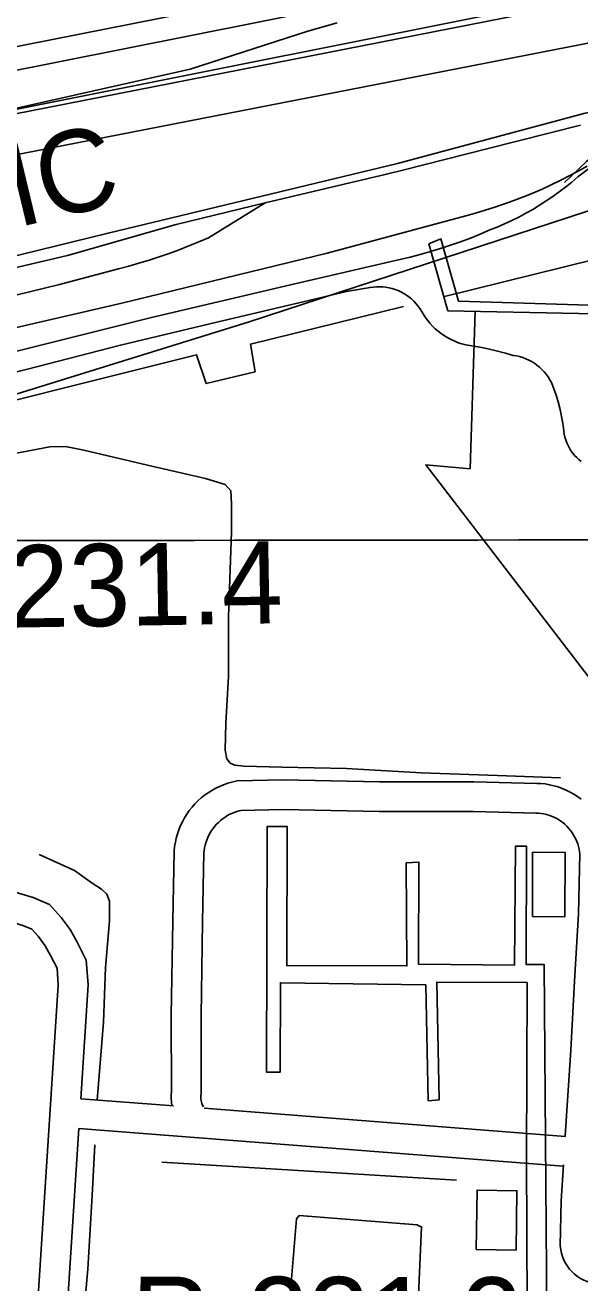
# Model space of a CAD drawing. Extents: x 3313447 to 3351316, y 703786 to 729172.
# Drawn here: x 3320817 to 3321377, y 720543 to 721813 of the extents above; entities that cross this region are included whole.
import ezdxf

# ---------------------------------------------------------------- set-up
doc = ezdxf.new("R2010")
doc.units = 0
for name, color, linetype in [('V-BLDG-OTLN', 7, 'Continuous'), ('V-DTCH-CNTR', 7, 'Continuous'), ('V-GRID-MAJR', 7, 'Continuous'), ('V-RAIL-IDEN', 7, 'Continuous'), ('V-RAIL-TRAK', 7, 'Continuous'), ('V-RIVR-RANG-IDEN', 7, 'Continuous'), ('V-ROAD-CNTR', 7, 'Continuous'), ('V-SITE-OTLN', 7, 'Continuous'), ('V-SITE-VEGE', 7, 'Continuous'), ('V-TOPO-SHOR', 7, 'Continuous'), ('V-UTIL-LINE', 7, 'Continuous')]:
    doc.layers.add(name, color=color, linetype=linetype)

msp = doc.modelspace()

# ---------------------------------------------------------------- linework, layer by layer
at = {"layer": 'V-BLDG-OTLN'}
for points in [[(3321329.251, 720912.969), (3321329.421, 720977.929), (3321362.312, 720977.843), (3321362.146, 720912.883)], [(3321272.464, 720576.802), (3321273.441, 720636.827), (3321313.668, 720636.171), (3321312.691, 720576.147)]]:
    msp.add_lwpolyline(points, close=True, dxfattribs=at)
at = {"layer": 'V-DTCH-CNTR'}
for points in [[(3320715.056, 721440.591), (3320817.772, 721465.376), (3320913.178, 721490.181), (3321010.318, 721513.2440000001), (3321104.676, 721535.6140000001), (3321141.233, 721544.22), (3321165.254, 721548.332), (3321168.418, 721548.775), (3321171.605, 721549.0160000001), (3321174.799, 721549.057), (3321177.992, 721548.897), (3321181.167, 721548.535), (3321184.312, 721547.974), (3321187.417, 721547.214), (3321190.467, 721546.26), (3321193.451, 721545.115), (3321196.357, 721543.786), (3321199.171, 721542.274), (3321201.886, 721540.589), (3321204.489, 721538.733), (3321206.969, 721536.718), (3321209.318, 721534.551), (3321211.524, 721532.2390000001), (3321213.58, 721529.794), (3321215.481, 721527.223), (3321217.211, 721524.539), (3321218.77, 721521.747), (3321220.892, 721518.464), (3321223.194, 721515.304), (3321225.67, 721512.281), (3321228.312, 721509.402), (3321231.113, 721506.676), (3321234.0640000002, 721504.1140000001), (3321237.1550000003, 721501.7220000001), (3321240.376, 721499.508), (3321243.717, 721497.478), (3321247.168, 721495.6410000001), (3321250.715, 721494.003), (3321254.352, 721492.5650000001), (3321258.063, 721491.336), (3321261.835, 721490.321), (3321269.9390000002, 721489.071), (3321278.0100000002, 721487.617), (3321286.043, 721485.956), (3321294.028, 721484.093), (3321301.96, 721482.024), (3321309.828, 721479.757), (3321313.076, 721479.237), (3321316.281, 721478.504), (3321319.433, 721477.561), (3321322.518, 721476.417), (3321325.52, 721475.071), (3321328.426, 721473.531), (3321331.2260000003, 721471.807), (3321333.907, 721469.9), (3321336.4560000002, 721467.821), (3321338.865, 721465.581), (3321341.122, 721463.187), (3321343.215, 721460.649), (3321345.1380000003, 721457.983), (3321346.883, 721455.193), (3321348.4390000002, 721452.295), (3321350.938, 721445.93), (3321353.1950000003, 721439.479), (3321355.208, 721432.946), (3321356.977, 721426.341)], [(3321356.977, 721426.341), (3321358.4990000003, 721419.679), (3321359.769, 721412.961), (3321360.787, 721406.203), (3321361.0300000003, 721403.1900000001), (3321361.4790000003, 721400.2000000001), (3321362.13, 721397.2490000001), (3321362.978, 721394.3470000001), (3321364.02, 721391.511), (3321365.253, 721388.75), (3321366.6720000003, 721386.079), (3321368.268, 721383.511), (3321370.0330000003, 721381.058), (3321371.9620000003, 721378.7270000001), (3321374.043, 721376.536), (3321376.269, 721374.49), (3321378.631, 721372.5970000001)]]:
    msp.add_lwpolyline(points, dxfattribs=at)
at = {"layer": 'V-GRID-MAJR'}
msp.add_spline([(3317583.083, 721289.311), (3322833.044, 721295.0380000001), (3328083.005, 721301.528), (3333332.965, 721308.783), (3338582.924, 721316.8), (3343832.882, 721325.582), (3349082.838, 721335.127), (3349082.839, 721335.127)], degree=3, dxfattribs=at)
at = {"layer": 'V-RAIL-TRAK'}
for points in [[(3321377.887, 721712.283), (3321283.29, 721688.235), (3321199.705, 721667.135), (3321181.822, 721662.621), (3321059.225, 721633.8910000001), (3320969.3850000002, 721611.9450000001), (3320859.455, 721580.5430000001), (3320596.289, 721518.909)], [(3321419.0300000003, 721692.636), (3321375.11, 721660.006), (3321369.007, 721654.791), (3321362.765, 721649.747), (3321356.387, 721644.875), (3321349.879, 721640.179), (3321343.2430000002, 721635.661), (3321336.487, 721631.327), (3321329.616, 721627.1780000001), (3321322.634, 721623.221), (3321315.546, 721619.455), (3321308.358, 721615.883), (3321301.075, 721612.512), (3321293.702, 721609.338), (3321286.245, 721606.368), (3321276.452, 721602.184), (3321266.5700000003, 721598.213), (3321256.607, 721594.455), (3321246.563, 721590.914), (3321236.446, 721587.59), (3321226.2600000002, 721584.488), (3321216.007, 721581.604), (3321205.696, 721578.942), (3321195.3310000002, 721576.502), (3321084.886, 721550.911), (3320944.3200000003, 721518.003), (3320804.275, 721482.985)], [(3321384.47, 721670.88), (3321375.563, 721665.887), (3321366.556, 721661.077), (3321357.452, 721656.448), (3321348.259, 721652.008), (3321338.973, 721647.754), (3321329.606, 721643.691), (3321320.156, 721639.818), (3321310.631, 721636.14), (3321301.032, 721632.657), (3321291.365, 721629.367), (3321281.631, 721626.277), (3321271.84, 721623.383), (3321261.989, 721620.6900000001), (3321121.9390000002, 721583.029), (3320914.253, 721532.341), (3320784.256, 721502.576)], [(3320764.0300000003, 721530.027), (3320851.2260000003, 721551.453), (3320910.9450000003, 721567.143), (3320921.306, 721569.828), (3320931.612, 721572.72), (3320941.858, 721575.814), (3320952.041, 721579.1140000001), (3320962.156, 721582.612), (3320972.199, 721586.31), (3320982.169, 721590.21), (3320992.058, 721594.304), (3321001.864, 721598.594), (3321059.225, 721633.8910000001)]]:
    msp.add_lwpolyline(points, dxfattribs=at)
at = {"layer": 'V-ROAD-CNTR'}
for points in [[(3321599.017764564, 721774.9144231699), (3321486.4609896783, 721744.793483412), (3321382.659197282, 721724.407524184), (3321193.099576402, 721673.40962618), (3320900.4761616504, 721603.2987664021), (3320354.97225266, 721469.442034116), (3319853.704255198, 721345.2962824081), (3319482.2569980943, 721260.223452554), (3319347.642267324, 721225.1355227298), (3319071.498819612, 721155.4696620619), (3318801.6813592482, 721085.8358013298), (3318597.173768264, 721038.4098961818), (3318497.648967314, 721012.8879472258), (3318053.893854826, 720830.5203119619), (3317615.848730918, 720718.779535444), (3317581.334799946, 720710.5405519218)], [(3321378.57428082, 721031.4875044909), (3321375.0071688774, 721034.1262927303), (3321371.28895144, 721036.548881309), (3321367.4405012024, 721038.7463913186), (3321363.4667680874, 721040.7157744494), (3321359.3808405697, 721042.4483276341), (3321355.1983168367, 721043.9378909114), (3321350.941316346, 721045.1750426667), (3321346.6156204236, 721046.1630950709), (3321342.2369128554, 721046.8916300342), (3321337.828875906, 721047.3622700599), (3321333.666936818, 721047.5592849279), (3321269.9803972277, 721049.1241932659), (3321174.6075424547, 721049.0241609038), (3321077.0315982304, 721051.0202282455), (3321031.016589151, 721050.0519076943), (3321025.655509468, 721048.8433852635), (3321021.415429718, 721047.6289212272), (3321017.2572432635, 721046.1780743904), (3321013.188651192, 721044.497165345), (3321009.21795251, 721042.5867699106), (3321005.3637048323, 721040.455845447), (3321001.6323991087, 721038.1079740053), (3320998.0485367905, 721035.5567290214), (3320994.607112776, 721032.8085414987), (3320991.322880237, 721029.8606759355), (3320988.220311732, 721026.7407884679), (3320985.2970420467, 721023.453964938), (3320982.5587376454, 721020.0007276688), (3320980.020551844, 721016.3967021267), (3320977.69109692, 721012.6559444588), (3320975.5778403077, 721008.7898988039), (3320973.6876975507, 721004.8140385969), (3320972.0244740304, 721000.7388934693), (3320970.591017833, 720996.5698527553), (3320969.3976520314, 720992.3267743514), (3320968.4466708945, 720988.0287853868), (3320967.7399331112, 720983.6843902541), (3320967.253750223, 720979.0741251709), (3320966.0162567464, 720908.1271908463), (3320964.374753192, 720812.9940977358), (3320964.5216596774, 720735.9704318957), (3320964.2795957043, 720733.3925458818), (3320964.220828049, 720729.4966803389), (3320964.4664734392, 720725.6249091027), (3320964.9928644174, 720721.8873942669)], [(3321362.4572764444, 720690.905246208), (3321362.504857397, 720691.683104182), (3321367.9460574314, 720777.9365712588), (3321371.9541898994, 720847.8330040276), (3321375.941550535, 720915.7396278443), (3321377.1211383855, 720976.417861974), (3321376.8887279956, 720978.5487935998), (3321376.4426553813, 720981.1786695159), (3321375.8444354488, 720983.7739544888), (3321375.0904538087, 720986.3325356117), (3321374.187089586, 720988.8506633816), (3321373.140025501, 720991.3020693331), (3321371.949876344, 720993.6891255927), (3321370.620806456, 720996.001662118), (3321369.157127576, 720998.2347491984), (3321367.566509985, 721000.373829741), (3321365.8534179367, 721002.4140826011), (3321364.0187064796, 721004.3540212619), (3321362.0751408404, 721006.1818895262), (3321360.0257191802, 721007.8924955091), (3321357.8828311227, 721009.4777072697), (3321355.6490485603, 721010.933118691), (3321353.329498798, 721012.2576086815), (3321350.9392319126, 721013.4422255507), (3321348.483159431, 721014.4836723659), (3321345.971683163, 721015.3781090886), (3321343.408683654, 721016.1229573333), (3321340.8083795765, 721016.7169049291), (3321338.179087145, 721017.1543699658), (3321335.525124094, 721017.4377299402), (3321332.589063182, 721017.5767150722), (3321269.6276027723, 721019.1238067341), (3321174.3164575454, 721019.0238390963), (3321077.04040177, 721021.0137717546), (3321034.6674108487, 721020.1220923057), (3321033.090490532, 721019.7666147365), (3321030.494570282, 721019.0230787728), (3321027.9347567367, 721018.1299256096), (3321025.4293488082, 721017.094834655), (3321022.99004749, 721015.9212300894), (3321020.6222951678, 721014.612154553), (3321018.3336008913, 721013.1720259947), (3321016.12146321, 721011.5972709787), (3321014.0028872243, 721009.9054585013), (3321011.9951197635, 721008.1033240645), (3321010.081688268, 721006.1792115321), (3321008.2769579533, 721004.1500350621), (3321006.5952623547, 721002.0292723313), (3321005.037448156, 720999.8172978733), (3321003.60690308, 720997.5200555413), (3321002.308159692, 720995.1441011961), (3321001.144302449, 720992.6959614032), (3321000.1195259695, 720990.1851065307), (3320999.238982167, 720987.6241472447), (3320998.5063479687, 720985.0192256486), (3320997.9213291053, 720982.3752146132), (3320997.486066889, 720979.699609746), (3320997.226249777, 720977.2358748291), (3320996.0117432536, 720907.6068091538), (3320994.375246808, 720812.7639022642), (3320994.5243403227, 720734.5935681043), (3320994.258404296, 720731.7614541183), (3320994.2351719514, 720730.2213196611), (3320994.333526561, 720728.6710908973), (3320994.5502048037, 720727.1326182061), (3320994.883807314, 720725.6299909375), (3320995.3372757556, 720724.1480902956), (3320995.9035223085, 720722.705387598), (3320996.8335828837, 720720.792813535)], [(3320872.810216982, 720729.049514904), (3320880.2292021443, 720843.963285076), (3320878.395205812, 720869.115234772), (3320868.79622501, 720887.7441975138), (3320862.117238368, 720899.8461733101), (3320853.0932564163, 720912.07614885), (3320841.425279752, 720925.084122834), (3320824.705313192, 720932.3221083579), (3320800.7973610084, 720939.4320941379), (3320695.338571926, 720945.7020815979), (3320337.6882872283, 720967.9610370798), (3319663.292636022, 721016.2849404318), (3319634.021694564, 721018.9899350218), (3319621.0377205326, 721011.3589502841), (3319607.3897478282, 721001.008970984), (3319598.1027664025, 720988.234996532), (3319586.190790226, 720969.4510340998), (3319577.4098077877, 720951.9500691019), (3319567.714827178, 720725.8495213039), (3319552.01885857, 720445.6400817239), (3319549.110864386, 720392.5861878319)], [(3320796.6763692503, 720012.983947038), (3320811.634339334, 720247.1364787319), (3320850.159262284, 720843.8392853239), (3320848.92126476, 720860.82125136), (3320842.324277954, 720873.6222257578), (3320836.805288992, 720883.6222057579), (3320829.8033029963, 720893.1121867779), (3320823.479315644, 720900.162172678), (3320814.4333337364, 720904.0781648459), (3320795.5633714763, 720909.690153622), (3320693.51657557, 720915.758141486), (3320335.684291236, 720938.0270969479), (3319660.8406409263, 720986.383000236), (3319640.887680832, 720988.2279965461), (3319637.759687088, 720986.3890002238), (3319629.0477045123, 720979.7830134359), (3319622.926716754, 720971.365030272), (3319612.330737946, 720954.6550636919), (3319607.107748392, 720944.242084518), (3319597.67876725, 720724.3675242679), (3319581.9727986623, 720443.9800850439), (3319557.046848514, 719989.2089945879)], [(3320872.809216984, 720729.0515148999), (3320966.4530192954, 720721.7739172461)], [(3320997.589041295, 720719.3541581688), (3321362.575567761, 720690.9889591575)], [(3320818.182326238, 719879.071214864), (3320841.572279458, 720245.2144825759), (3320870.877220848, 720699.1105747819)], [(3320870.8762208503, 720699.11157478), (3321360.404845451, 720661.0671130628)], [(3321416.866038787, 720540.6497573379), (3321406.261176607, 720541.0337692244), (3321394.9922221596, 720541.8142514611), (3321391.455433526, 720542.3382201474), (3321387.9017979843, 720543.1807706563), (3321384.440553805, 720544.3303759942), (3321381.093674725, 720545.7689604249), (3321377.8778780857, 720547.4964801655), (3321374.829529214, 720549.4904662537), (3321371.9651931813, 720551.7379160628), (3321369.297970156, 720554.2297047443), (3321366.8580109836, 720556.9430138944), (3321364.6598030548, 720559.8573870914), (3321362.727696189, 720562.9453493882), (3321361.067432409, 720566.1807748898), (3321359.685502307, 720569.5648714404), (3321358.6062053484, 720573.0493258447), (3321357.82871005, 720576.6084577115), (3321357.2955400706, 720580.7391965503), (3321358.4900771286, 720626.0015168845), (3321360.7088298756, 720662.3104891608)]]:
    msp.add_lwpolyline(points, dxfattribs=at)
msp.add_arc((3321675.579507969, 721345.1257904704), 440.5884812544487, 114.14058874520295, 135.43627763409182, dxfattribs=at)
at = {"layer": 'V-SITE-OTLN'}
msp.add_lwpolyline([(3322017.001, 719673.736), (3320119.971, 719808.487), (3319440.938, 719820.238), (3319430.9790000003, 719830.251), (3319553.977, 721048.247), (3319573.9760000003, 721058.182), (3321043.134, 721513.729), (3321922.666, 721801.0430000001), (3321982.5840000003, 721800.887), (3322002.452, 721760.892), (3322097.018, 719723.46)], close=True, dxfattribs=at)
at = {"layer": 'V-SITE-VEGE'}
msp.add_lwpolyline([(3321131.937, 721815.674), (3321102.218, 721807.179), (3320983.346, 721768.9450000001), (3320605.5, 721683.979)], dxfattribs=at)
at = {"layer": 'V-TOPO-SHOR'}
for points in [[(3321357.69, 721053.2000000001), (3321294.116, 721055.532), (3321216.818, 721058.26), (3321141.329, 721062.43), (3321075.947, 721064.046), (3321037.657, 721064.867), (3321028.63, 721065.975), (3321023.938, 721067.794), (3321020.3370000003, 721072.137), (3321018.916, 721081.1730000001), (3321019.348, 721108.264), (3321021.998, 721155.581), (3321022.154, 721215.547), (3321025.269, 721301.515), (3321025.34, 721329.692), (3321024.6520000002, 721343.059), (3321018.889, 721349.215), (3320999.038, 721355.409), (3320940.1890000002, 721368.927), (3320875.927, 721383.904), (3320857.5130000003, 721387.566), (3320841.616, 721387.245), (3320808.005, 721380.83), (3320746.612, 721368.524)], [(3320830.809, 720975.691), (3320866.5160000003, 720959.4670000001), (3320884.545, 720946.777), (3320893.92, 720940.611), (3320899.327, 720935.54), (3320901.838, 720928.671), (3320901.785, 720908.801), (3320897.6890000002, 720861.49), (3320895.739, 720806.225), (3320889.5130000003, 720727.492)], [(3320887.113, 720682.606), (3320884.446, 720631.412), (3320879.92, 720557.008), (3320873.965, 720489.469), (3320872.359, 720428.062)], [(3321195.818, 720422.182), (3321081.267, 720432.524), (3321080.356, 720432.981), (3321078.539, 720437.096), (3321083.3170000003, 720518.794), (3321090.852, 720607.79), (3321093.6, 720610.979), (3321212.718, 720601.54), (3321214.543, 720600.62), (3321217.2770000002, 720599.701), (3321210.0130000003, 720438.58), (3321208.157, 720427.63), (3321205.87, 720425.3520000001), (3321203.5840000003, 720424.4450000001), (3321195.818, 720422.182)]]:
    msp.add_lwpolyline(points, dxfattribs=at)
at = {"layer": 'V-UTIL-LINE'}
for p, q in [((3319986.044, 721562.216), (3327138.821, 722968.4670000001)), ((3320012.086, 721527.4940000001), (3327138.821, 722916.384)), ((3320480.835, 721727.147), (3326505.1410000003, 722916.384)), ((3320472.1550000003, 721701.105), (3326453.059, 722890.3420000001)), ((3320498.198, 721666.383), (3326435.696, 722855.62)), ((3320954.924, 720664.886), (3321252.507, 720646.7660000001))]:
    msp.add_line(p, q, dxfattribs=at)
for points in [[(3321920.64, 721651.838), (3321890.461, 721661.582), (3321698.3340000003, 721652.416), (3321238.926, 721538.832)], [(3321622.722, 720876.252), (3321621.784, 720980.16), (3321598.828, 720980.2170000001), (3321601.525, 721087.7390000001), (3321608.795, 721096.179), (3321614.284, 721348.677), (3321511.603, 721354.985), (3321518.069, 721518.073), (3321551.896, 721516.777), (3321551.916, 721525.235), (3321254.727, 721534.463), (3321236.768, 721597.337), (3321224.6720000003, 721592.534), (3321243.827, 721524.827), (3321508.406, 721519.306), (3321505.541, 721346.5430000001)], [(3321199.031, 721529.269), (3321044.284, 721491.011), (3321049.044, 721463.209), (3320999.4760000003, 721451.257), (3320989.8880000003, 721480.277), (3320684.017, 721403.75), (3320208.895, 721287.79), (3320051.732, 721249.535), (3320058.9020000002, 721219.313), (3320006.919, 721207.365), (3319998.537, 721236.383), (3319680.579, 721157.469), (3319664.895, 721153.572)], [(3321581.878, 721020.182), (3321487.648, 721022.8420000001), (3321221.537, 721369.077), (3321266.23, 721365.337), (3321271.5100000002, 721524.25)], [(3321325.633, 720136.996), (3321323.365, 720670.181), (3321323.824, 720846.382), (3321232.526, 720846.622), (3321234.957, 720727.9280000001), (3321223.9990000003, 720727.0430000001), (3321221.563, 720843.91), (3321074.5810000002, 720846.118), (3321074.345, 720755.734), (3321060.65, 720755.7710000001), (3321061.2970000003, 721004.0970000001), (3321081.382, 721004.045), (3321081.017, 720863.448), (3321202.441, 720863.133), (3321201.798, 720967.212), (3321214.5840000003, 720968.093), (3321214.316, 720864.927), (3321311.088, 720863.764), (3321312.312, 720984.272), (3321323.269, 720984.243), (3321322.958, 720864.644), (3321341.218, 720864.5970000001), (3321346.682, 720157.027)]]:
    msp.add_lwpolyline(points, dxfattribs=at)

# ---------------------------------------------------------------- texts
at = {"layer": 'V-RAIL-IDEN'}
msp.add_text('PACIFIC', height=82.999832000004, rotation=13.512472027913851, dxfattribs=at).set_placement((3320490.43198174, 721532.2262345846))
at = {"layer": 'V-RIVR-RANG-IDEN'}
for s, height, rotation, p in [('R-231.4', 82.99999800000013, 0.9353583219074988, (3320682.818329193, 721202.8452714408)), ('R-231.2', 82.99999799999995, 359.8738403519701, (3320923.9530186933, 720466.4622307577))]:
    msp.add_text(s, height=height, rotation=rotation, dxfattribs=at).set_placement(p)

doc.saveas('drawing.dxf')
